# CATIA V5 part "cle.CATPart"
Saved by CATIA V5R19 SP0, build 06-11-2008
Part number: clé
Bounding box of the stored display mesh (mm): x -110 to 20, y -55.143 to 5, z -106.748 to 5
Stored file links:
  F:\CFAO\Hberriche\cle.CATPart
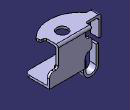
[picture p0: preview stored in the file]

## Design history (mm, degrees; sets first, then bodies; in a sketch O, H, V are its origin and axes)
Body1 (main body)
  Sketch1 on zx-plane, origin (0, 0, 0), H (-1, 0, 0), V (0, 0, 1)
    line L1 (0, 0) -> (60, 0)
    point P1 (0, 0)
    line L2 (0, 0) -> (0, -35)
    point P3 (0, -40)
    line L3 (-5, -40) -> (-10, -40)
    point P4 (-20, -40)
    line L4 (-20, -50) -> (-20, -70)
    point P5 (-20, -70)
    line L5 (-20, -70) -> (60, -70)
    point P6 (60, -70)
    line L6 (60, 0) -> (60, -5)
    point P7 (60, -15)
    line L7 (70, -15) -> (70, -15)
    point P8 (75, -15)
    line L8 (75, -20) -> (75, -35)
    point P9 (75, -15)
    point P10 (75, -40)
    line L9 (70, -40) -> (70, -40)
    point P11 (60, -40)
    line L10 (60, -50) -> (60, -70)
    arc A1 centre (-10, -50) radius 10 from (-20, -50) to (-10, -40) cw
    arc A2 centre (70, -50) radius 10 from (60, -50) to (70, -40) cw
    arc A3 centre (70, -5) radius 10 from (60, -5) to (70, -15) ccw
    arc A4 centre (70, -20) radius 5 from (70, -15) to (75, -20) cw
    arc A5 centre (70, -35) radius 5 from (70, -40) to (75, -35) ccw
    arc A6 centre (-5, -35) radius 5 from (-5, -40) to (0, -35) ccw
    length L1 = 60
    distance P4 P5 = 30
    distance P3 P4 = 20
    radius A1 = 10
    distance P11 P6 = 30
    distance P10 P11 = 15
    radius A2 = 10
    radius A3 = 10
    radius A4 = 5
    radius A5 = 5
    distance P1 P3 = 40
    radius A6 = 5
    length L6 = 5
    horizontal: L1 H, L3 H, L5 H, L7 H, L9 H
    vertical: L2 V, L4 V, L6 V, L8 V, L10 V
    coincidence: P9 L7, P9 P8, P11 L6, L2 V, H L1, L4 P4, L3 P4, L10 P11, L9 P11, L6 P7, L7 P7, L7 P8, L8 P9, L9 P10, L8 P10, L3 P3, L2 P3
    tangency: A1 L4, A1 L3, A2 L10, A2 L9, A3 L6, A3 L7, A4 L7, A4 L8, A5 L9, A5 L8, A6 L3, A6 L2
  Pad1: profile Sketch1, direction (0, 1, 0), length 5
  Sketch2 on face of Pad1 from Sketch1.L1, origin (0, 0, 0), H (1, 0, 0), V (0, 1, 0)
    line L1 (-75, 5) -> (0, 5)
    point P1 (0, 5)
    line L2 (0, 5) -> (0, -25)
    line L3 (-75, 5) -> (-75, -9.3228)
    line L4 (0, -25) -> (10, -25)
    line L5 (10, -25) -> (10, -35)
    point P7 (-75, -11.9916)
    reference projected line E1 (-60, 5) -> (0, 5) from edge [face of Pad1 from Sketch1.L1 | end face of Pad1]
    reference projected line E2 (-75, 0) -> (-75, 5) from edge [face of Pad1 from Sketch1.A4 | face of Pad1 from Sketch1.L8]
    line L6 (-75, -9.3228) -> (-105, -9.3228)
    line L7 (-105, -9.3228) -> (-105, -27.3228)
    line L8 (-105, -27.3228) -> (-95, -27.3228)
    arc A1 centre (-39.1353, 14.857) radius 70 from (10, -35) to (-95, -27.3228) cw
    point P12 (-75, -45.2573)
    length L7 = 18
    length L4 = 10
    length L5 = 10
    length L6 = 30
    length L8 = 10
    radius A1 = 70
    length L2 = 30
    coincidence: P1 V, P7 L3, E1 L1, E2 L3, A1 P12, P12 L3
    horizontal: L1 H, L4 H, L6 H, L8 H
    vertical: L2 V, L3 V, L5 V, L7 V
  Pad2: profile Sketch2, direction (0, 0, 1), length 5
  Fillet1: radius 5, on edge [start face of Pad2 | face of Pad1 from Sketch1.L6]
  Fillet2: radius 5, on edge [face of Pad2 | end face of Pad2]
  Fillet3: radius 3, on edge [start face of Pad2 | face of Pad2 from Sketch2.L3]
  Fillet4: radius 3, on edge [face of Pad2 from Sketch2.L6 | face of Pad2 from Sketch2.L3]
  Fillet5: radius 3, on edge [face of Pad2 from Sketch2.A1 | face of Pad2 from Sketch2.L8]
  Fillet6: radius 3, on edge [face of Pad2 from Sketch2.L5 | face of Pad2 from Sketch2.A1]
  Fillet7: radius 3, on edge [face of Pad2 from Sketch2.L4 | face of Pad2 from Sketch2.L5]
  Fillet8: radius 3, on edge [face of Pad2 | face of Pad2 from Sketch2.L4]
  Sketch3 on face of Pad2 from Sketch2.L6, origin (0, -9.3228, 0), H (-1, 0, 0), V (0, 0, 1)
    line L1 (105, 5) -> (105, -40)
    line L2 (105, -40) -> (110, -40)
    line L3 (110, -40) -> (110, 5)
    point P4 (110, 5)
    line L4 (105, 5) -> (110, 5)
    point P5 (110, 5)
    reference projected line E1 (105, 0) -> (105, 5) from edge [face of Pad2 from Sketch2.L7 | face of Pad2 from Sketch2.L6]
    reference projected line E2 (75, 5) -> (105, 5) from edge [face of Pad2 from Sketch2.L6 | end face of Pad2]
    reference projected point E3 (70, -40) from vertex [face of Pad1 from Sketch1.A5 | end face of Pad1 | face of Pad1 from Sketch1.A2]
    length L2 = 5
    vertical: L1 V, L3 V
    horizontal: L2 H, L4 H
    coincidence: P5 L3, E1 L1, E2 L4, P5 P4, E3 L2
  Pad3: profile Sketch3, direction (0, -1, 0), length 18
  Fillet9: radius 5, on edge [face of Pad3 from Sketch3.L3 | face of Pad3]
  Fillet10: radius 5, on edge [start face of Pad2 | face of Pad3 from Sketch3.L1]
  Sketch4 on face of Pad2, origin (0, 5, 0), H (-1, 0, 0), V (0, 0, 1)
    line L1 (60, -70) -> (66.5366, -70)
    line L2 (71.5366, -75) -> (71.5366, -92.6245)
    line L3 (60, -65) -> (71.5366, -65)
    line L4 (76.5366, -70) -> (76.5366, -92.1917)
    line L5 (100, -50) -> (100, -89.9635)
    line L6 (100, -50) -> (105, -50)
    line L7 (105, -50) -> (105, -89.9635)
    reference projected line E1 (105, -5) -> (105, -40) from edge [face of Pad3 from Sketch3.L1 | face of Pad3]
    arc A1 centre (88.1625, -89.9635) radius 11.8375 from (76.5366, -92.1917) to (100, -89.9635) ccw
    point P9 (88.1625, -89.9635)
    arc A2 centre (88.1625, -89.9635) radius 16.8375 from (71.5366, -92.6245) to (105, -89.9635) ccw
    point P10 (88.1625, -89.9635)
    line L8 (60, -70) -> (60, -65)
    reference projected line E2 (60, -70) -> (60, -50) from edge [face of Pad1 from Sketch1.L10 | end face of Pad1]
    reference projected line E3 (105, -5) -> (105, -40) from edge [face of Pad3 from Sketch3.L1 | face of Pad3]
    reference projected line E4 (105, -40) -> (110, -40) from edge [face of Pad3 from Sketch3.L2 | start face of Pad3]
    reference projected line E5 (-20, -70) -> (60, -70) from edge [face of Pad1 from Sketch1.L5 | end face of Pad1]
    arc A3 centre (71.5366, -70) radius 5 from (71.5366, -65) to (76.5366, -70) cw
    arc A4 centre (66.5366, -75) radius 5 from (66.5366, -70) to (71.5366, -75) cw
    length L6 = 5
    distance L3 L1 = 5
    distance L2 L4 = 5
    distance E4 L6 = 10
    radius A3 = 5
    radius A4 = 5
    horizontal: L1 H, L3 H, L6 H
    vertical: L2 V, L4 V, L5 V, L7 V, L8 V
    coincidence: E1 L7, P10 P9, E2 L8, E3 L7, E5 L1
    tangency: A1 L5, A2 L7, A3 L3, A3 L4, A4 L1, A4 L2
  Pad4: profile Sketch4, direction (0, -1, 0), length 30, opposite side length -15
  Fillet11: radius 5, on edge [start face of Pad1 | start face of Pad2]
  Sketch5 on face of Pad1 from Sketch1.L5, origin (0, 0, -70), H (1, 0, 0), V (0, -1, 0)
    line L1 (-50, 50.8269) -> (10, 50.8269)
    line L2 (20, 40.8269) -> (20, -5)
    line L3 (20, -5) -> (-60, -5)
    line L4 (-60, -5) -> (-60, 40.8269)
    reference projected line E1 (20, -5) -> (-60, -5) from edge [face of Pad1 from Sketch1.L5 | end face of Pad1]
    reference projected line E2 (-60, 2.632) -> (-60, 22.632) from edge [face of Pad4 from Sketch4.L8 | face of Pad4 from Sketch4.L1]
    reference projected line E3 (20, 0) -> (20, -5) from edge [face of Pad1 from Sketch1.L5 | face of Pad1 from Sketch1.L4]
    arc A1 centre (-50, 40.8269) radius 10 from (-60, 40.8269) to (-50, 50.8269) cw
    arc A2 centre (10, 40.8269) radius 10 from (10, 50.8269) to (20, 40.8269) cw
    radius A1 = 10
    radius A2 = 10
    horizontal: L1 H, L3 H
    vertical: L2 V, L4 V
    coincidence: E1 L3, E2 L4, E3 L2
    tangency: A1 L4, A1 L1, A2 L1, A2 L2
  Pad5: profile Sketch5, direction (0, 0, 1), length 5
  Fillet12: radius 5, on edge [end face of Pad4 | face of Pad5 from Sketch5.L4]
  Sketch6 on face of Pad3, origin (0, 0, 5), H (1, 0, 0), V (0, 1, 0)
    circle A1 centre (-33.0772, -19.1558) radius 12.5
    reference projected circle E1 centre (-33.0772, -19.1558) radius 10 from edge of DatumCurve1
    radius A1 = 12.5
    concentricity: E1 A1
  Pocket1: profile Sketch6, direction (0, 0, -1), through (limit type 3)
  Sketch7 on face of Pad3, origin (0, 0, 5), H (1, 0, 0), V (0, 1, 0)
    point P1 (-33.0772, -19.1558)
    reference projected circle E1 centre (-33.0772, -19.1558) radius 12.5 from edge [face of Pad3 | face of Pocket1 from Sketch6.A1]
    concentricity: E1 P1
  Plane1: type Tangent, Support face of Pad3, RefPoint Sketch7
  DatumCurve1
